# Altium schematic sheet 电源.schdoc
size 420 x 297 mm; Symbol: Drawing-Symbol_A4; Company: 嘉立创EDA; Version: V1.0; Page Size: A4; @Project Name: FOC; @Update Date: 2026-07-14; @Create Date: 2026-07-14; Device: Drawing-Symbol_A4; @Board Name: Board1; @Page Name: P1; @Create Time: 03:45:48; @Page Count: 1; @Page No: 1; @Schematic Name: Schematic1; @Update Time: 03:45:48; @Assembly Variant: Basic; Border: 1; Title Block Position: 3; Size: A4; Width: 1655; Height: 1170; Region Start: 1; X Region Count: 6; Y Region Count: 4; Blade Width: 10
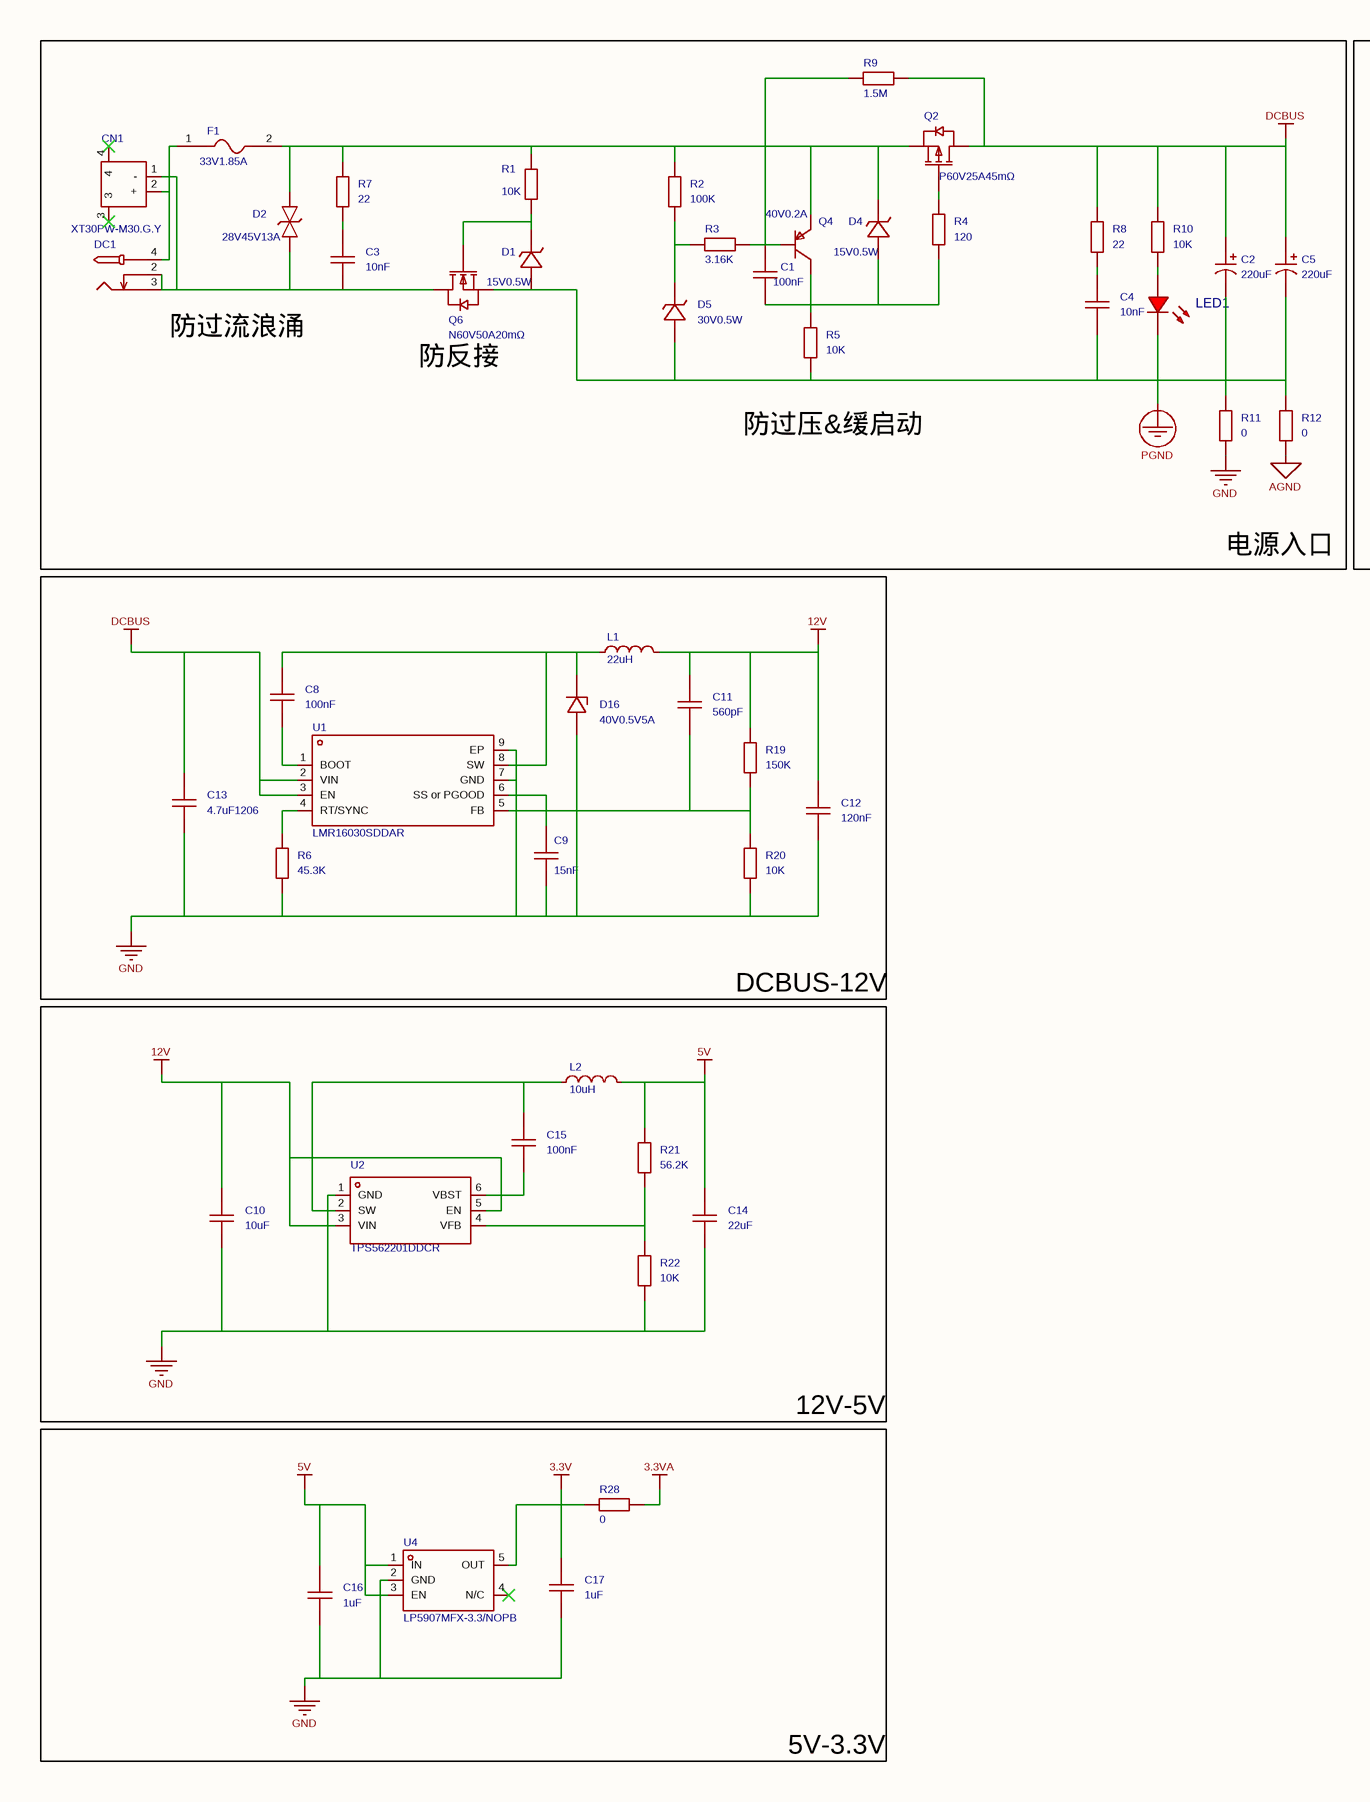
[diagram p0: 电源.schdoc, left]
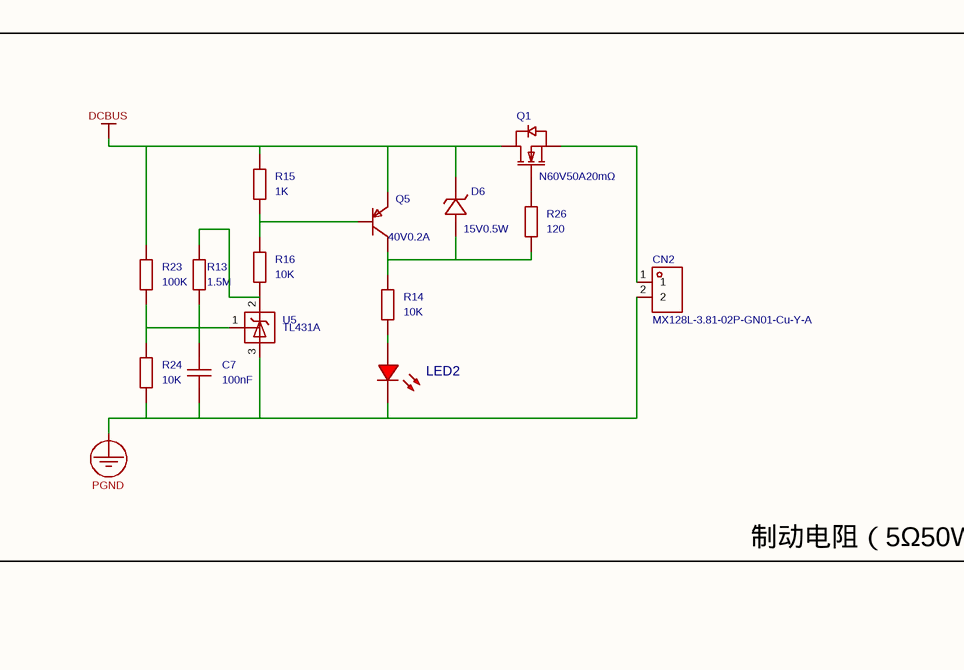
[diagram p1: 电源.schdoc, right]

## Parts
C1  100nF  [C0603]
C2  220uF  [CAP-SMD_BD10.0-L10.3-W10.3-FD-LS11.0]
C3  10nF  [C0603]
C4  10nF  [C0603]
C5  220uF  [CAP-SMD_BD10.0-L10.3-W10.3-FD-LS11.0]
C7  100nF  [C0603]
C8  100nF  [C0603]
C9  15nF  [C0603]
C10  10uF  [C0603]
C11  560pF  [C0603]
C12  120nF  [C0603]
C13  4.7uF1206  [C1206]
C14  22uF  [C0603]
C15  100nF  [C0603]
C16  1uF  [C0603]
C17  1uF  [C0603]
CN1  XT30PW-M30.G.Y  [CONN-TH_XT30PW-M]
CN2  MX128L-3.81-02P-GN01-Cu-Y-A  [CONN-TH_2P-P3.81_MX128L-3.81-GN01-02P-CU-Y-A]
D1  15V0.5W  [LL-34_L3.5-W1.5-RD-2]
D2  28V45V13A  [SMB_L4.6-W3.6-LS5.4-BI]
D4  15V0.5W  [LL-34_L3.5-W1.5-RD-2]
D5  30V0.5W  [LL-34_L3.5-W1.5-RD]
D6  15V0.5W  [LL-34_L3.5-W1.5-RD-2]
D16  40V0.5V5A  [SMA_L4.3-W2.6-LS5.0-FD]
DC1  (no value)  [DC-2.0]
F1  33V1.85A  [F2920]
L1  22uH  [IND-SMD_L5.5-W5.2]
L2  10uH  [IND-SMD_L4.4-W4.2]
LED1  (no value)  [LED_0603]
LED2  (no value)  [LED_0603]
Q1  N60V50A20mΩ  [TO-252-2_L6.6-W6.1-P4.57-LS10.1-TL-CW]
Q2  P60V25A45mΩ  [TO-252-2_L6.6-W6.1-P4.57-LS9.9-TL-CW]
Q4  40V0.2A  [SOT-23-3_L2.9-W1.3-P1.90-LS2.4-BR]
Q5  40V0.2A  [SOT-23-3_L2.9-W1.3-P1.90-LS2.4-BR]
Q6  N60V50A20mΩ  [TO-252-2_L6.6-W6.1-P4.57-LS10.1-TL-CW]
R1  10K  [R0603]
R2  100K  [R0603]
R3  3.16K  [R0603]
R4  120  [R0603]
R5  10K  [R0603]
R6  45.3K  [R0603]
R7  22  [R0603]
R8  22  [R0603]
R9  1.5M  [R0603]
R10  10K  [R0603]
R11  0  [R0603]
R12  0  [R0603]
R13  1.5M  [R0603]
R14  10K  [R0603]
R15  1K  [R0603]
R16  10K  [R0603]
R19  150K  [R0603]
R20  10K  [R0603]
R21  56.2K  [R0603]
R22  10K  [R0603]
R23  100K  [R0603]
R24  10K  [R0603]
R26  120  [R0603]
R28  0  [R0603]
U1  LMR16030SDDAR  [SOIC-8_L4.9-W3.9-P1.27-LS6.0-BL-EP2.3]
U2  TPS562201DDCR  [SOT-23-6_L2.9-W1.6-P0.95-LS2.8-BR]
U4  LP5907MFX-3.3/NOPB  [SOT-23-5_L3.0-W1.7-P0.95-LS2.8-BR]
U5  TL431A  [SOT-23-3_L3.0-W1.7-P0.95-LS2.9-BR]

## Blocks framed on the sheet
制动电阻（5Ω50W）: C7 CN2 D6 LED2 Q1 Q5 R13-R16 R23 R24 R26 U5
DCBUS-12V: C8 C9 C11-C13 D16 L1 R6 R19 R20 U1

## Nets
3.3V: C17.2 R28.1 U4.5(OUT)
3.3VA: R28.2
5V: C14.2 C16.2 L2.2 R21.2 U4.1(IN) U4.3(EN)
12V: C10.2 C11.2 C12.2 L1.2 R19.2 U2.3(VIN) U2.5(EN)
AGND: R12.1
DCBUS: C2.1 C5.1 C13.2 D6.1(K) Q1.2(D) Q2.2(D) Q5.2(E) R8.2 R9.2 R10.2 R15.2 R23.2 U1.2(VIN) U1.3(EN)
GND: C9.1 C10.1 C12.1 C13.1 C14.1 C16.1 C17.1 D16.1(A) R6.1 R11.1 R20.1 R22.1 U1.7(GND) U1.9(EP) U2.1(GND) U4.2(GND)
PGND: C2.2 C4.1 C5.2 C7.1 CN2.2 D1.2(A) D5.2(A) LED1.1(C) LED2.1(C) Q6.3(S) R5.1 R11.2 R12.2 R24.1 U5.3(A)
NetC1_1: C1.1 D4.2(A) Q4.3(C) R4.1 R5.2
NetC1_2: C1.2 Q4.1(B) R3.2 R9.1
NetC3_1: C3.1 CN1.1(-) D2.1 DC1.2 DC1.3 Q6.2(D)
NetC3_2: C3.2 R7.1
NetC4_2: C4.2 R8.1
NetC7_2: C7.2 R13.1 R23.1 R24.2 U5.1(R)
NetC8_1: C8.1 U1.1(BOOT)
NetC8_2: C8.2 D16.2(K) L1.1 U1.8(SW)
NetC9_2: C9.2 U1.6(SS_or_PGOOD)
NetC11_1: C11.1 R19.1 R20.2 U1.5(FB)
NetC15_1: C15.1 U2.6(VBST)
NetC15_2: C15.2 L2.1 U2.2(SW)
NetCN1_2: CN1.2(+) DC1.4 F1.1
NetCN2_1: CN2.1 Q1.3(S)
NetD1_1: D1.1(K) Q6.1(G) R1.1
NetD2_2: D2.2 D4.1(K) F1.2 Q2.3(S) Q4.2(E) R1.2 R2.2 R7.2
NetD5_1: D5.1(C) R2.1 R3.1
NetD6_2: D6.2(A) Q5.3(C) R14.1 R26.1
NetLED1_2: LED1.2(A) R10.1
NetLED2_2: LED2.2(A) R14.2
NetQ1_1: Q1.1(G) R26.2
NetQ2_1: Q2.1(G) R4.2
NetQ5_1: Q5.1(B) R15.1 R16.1
NetR6_2: R6.2 U1.4(RT/SYNC)
NetR13_2: R13.2 R16.2 U5.2(K)
NetR21_1: R21.1 R22.2 U2.4(VFB)

Not connected (* = marked no-connect by the designer): CN1 3* 4*; U4 4(N/C)*

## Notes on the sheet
- (near DC1) 防过流浪涌
- (near Q6) 防反接
- (near R5) 防过压&缓启动
- 电源入口
- 12V-5V
- 5V-3.3V

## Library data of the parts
C1 C3 C4 = CAP_0603: Symbol: Capacitance; ConvertToPcb: yes; ModelId: ac125912035d415993ca9572d50418b10819f05c4eef4c71ace90d822a990e87; ModelName: C0603_L1.6-W0.8-H0.8; ModelTransform: 62.992,31.496,0,0,0,0,0,0,0
C2 C5 = JVJ63V220M10x10: 容值:220uF;精度:±20%;额定电压:63V;纹波电流:225mA@120Hz;; Manufacturer: JIERR(捷而瑞); AddInBom: yes; ModelId: c5805980ffa24e6da624be5898d1d67f0819f05c4eef4c71ace90d822a990e87; ModelTransform: 433.07,405.511,0,180,0,0,0,0,0; Tolerance: ±20%; Voltage Rating: 63V; Lifetime: 2000hrs@105℃
C7-C12 C14-C17 = CAP_0603: Symbol: Capacitance; 3D Model: ac125912035d415993ca9572d50418b10819f05c4eef4c71ace90d822a990e87; 3D Model Transform: 62.992,31.496,0,0,0,0,0,0,0; ConvertToPcb: yes; ModelName: C0603_L1.6-W0.8-H0.8
C13 = CAP_1206: Symbol: Capacitance; 3D Model: e4be705b945545a48e666415e3682bd80819f05c4eef4c71ace90d822a990e87; 3D Model Transform: 125.984,62.992,0,0,0,0,0,0,0; ConvertToPcb: yes; ModelName: C1206_L3.2-W1.6-H1.3
CN1 = XT30PW-M30.G.Y: Socket,DCsupply,XT30,male,PIN:2; Manufacturer: AMASS(艾迈斯); AddInBom: yes; ModelId: 722652c2597f41cd937322584dc4b29b0819f05c4eef4c71ace90d822a990e87; ModelTransform: 523.621,549.2115,0,0,0,0,-0.005,-39.568,-78.74; Rated current: 15A; Rated voltage: 500VDC; Connector type: 航模插头; Wire gauge: 16/18/20AWG; contact resistance: 1.2mΩ; interface form: 公头
CN2 = MX128L-3.81-02P-GN01-Cu-Y-A: 结构:1x2P;间距:3.81mm;颜色:绿色;安装方式:直插;排数:1;每排PIN数:2;额定电流:10A;额定电压:150V;线规 - AWG:16~26;线规 - 平方毫米:1.5;工作温度范围:-40℃~+105℃;; Manufacturer: MAX(迈旭); Symbol: MX128L-3.81-GN01-02P-CU-Y-A; 3D Model: 3ada76795bf04056bedcd0ec9f9046df0819f05c4eef4c71ace90d822a990e87; 3D Model Transform: 300.3931,291.338,0,0,0,0,0,-11.811,-137.795; Structure: 1x2P; Pitch: 3.81mm; Number of PINs Per Row: 2; Screw Specification: M2; Current Rating (Max): 10A; Voltage Rating (Max): 150V; Wire Gauge - AWG: 16~26; Wire Gauge - mm2: 1.5; AddInBom: yes
D1 = ZMM15V: 二极管配置:1个独立式;稳压值(标称值):15V;稳压值(范围):13.8V~15.6V;耗散功率(Pd):500mW;; Manufacturer: YONGYUTAI(永裕泰); AddInBom: yes; ModelId: cdb89680927740768e9f4c53865b044a0819f05c4eef4c71ace90d822a990e87; ModelTransform: 137.795,59.055,0,0,0,0,0,0,0; Diode Configuration: 1个独立式; Zener Voltage(Nom): 15V; Reverse Leakage Current (Ir): 100nA@11V; Pd - Power Dissipation: 500mW; Impedance(Zzt): 30Ω; Impedance(Zzk): 110Ω; Operating Junction Temperature Range: -55℃~+150℃
D2 = SMBJ28CA_C19077583: 极性:双向;反向截止电压(Vrwm):28V;钳位电压:45.4V;峰值脉冲电流(Ipp):13.22A@10/1000us;峰值脉冲功率(Ppp):600W@10/1000us;击穿电压:34.4V;; Manufacturer: R+O(宏嘉诚); AddInBom: yes; ModelId: 56a671846d664f15ac0751d5510bb56a0819f05c4eef4c71ace90d822a990e87; ModelTransform: 212.598,142.5194,0,0,0,0,0,0,0; Polarity: 双向; Reverse Stand-Off Voltage (Vrwm): 28V; Clamping Voltage: 45.4V; Voltage - Breakdown: 34.4V; Reverse Leakage Current (Ir): 5uA; level of protection: IEC 61000-4-2; Type: TVS
D4 D6 = ZMM15V: 二极管配置:1个独立式;稳压值(标称值):15V;稳压值(范围):13.8V~15.6V;耗散功率(Pd):500mW;; Manufacturer: YONGYUTAI(永裕泰); 3D Model: cdb89680927740768e9f4c53865b044a0819f05c4eef4c71ace90d822a990e87; 3D Model Transform: 137.795,59.055,0,0,0,0,0,0,0; Diode Configuration: 1个独立式; Zener Voltage(Nom): 15V; Reverse Leakage Current (Ir): 100nA@11V; Pd - Power Dissipation: 500mW; Impedance(Zzt): 30Ω; Impedance(Zzk): 110Ω; Operating Junction Temperature Range: -55℃~+150℃; AddInBom: yes
D5 = ZMM30V: 二极管配置:1个独立式;稳压值(标称值):30V;稳压值(范围):28V~32V;耗散功率(Pd):500mW;; Manufacturer: JSMSEMI(杰盛微); AddInBom: yes; ModelId: 4a6f2309ca4c4217857da1816cccdf690819f05c4eef4c71ace90d822a990e87; ModelName: LL-34_L3.5-W1.5; ModelTransform: 133.93674,59.031,0,0,0,0,0,0,0; Diode Configuration: 1个独立式; Zener Voltage(Nom): 30V; Reverse Leakage Current (Ir): 100nA@22V; Pd - Power Dissipation: 500mW; Impedance(Zzt): 80Ω; Impedance(Zzk): 220Ω
D16 = SS54_C7420369: 二极管配置:独立式;正向压降(Vf):550mV@5A;直流反向耐压(Vr):40V;整流电流:5A;; Manufacturer: R+O(宏嘉诚); 3D Model: 7e24bebe6cd74171ae8c9de6fc5b78aa0819f05c4eef4c71ace90d822a990e87; 3D Model Transform: 198.4248,103.5431,0,180,0,0,-0.001,0,0; Diode Configuration: 独立式; Voltage - DC Reverse(Vr): 40V; Current - Rectified: 5A; Reverse Leakage Current (Ir): 50uA@40V; Operating Junction Temperature Range: -55℃~+125℃; Non-Repetitive Peak Forward Surge Current: 120A; AddInBom: yes
DC1 = DC-005_2.0: Symbol: DC电源接口; ConvertToPcb: yes; ModelId: f5f20b8a2308479b936ba3c2698865bb0819f05c4eef4c71ace90d822a990e87; ModelName: DC-IN-TH_DC-5520-1; ModelTransform: 372.05,551.18,582.68,90,0,0,137.8,0,-149.61
F1 = SMD2920P185TF: 耐压(Vmax):33V;最大电流(Imax):40A;保持电流(Ihold):1.85A;跳闸电流(Itrip):3.7A;; Manufacturer: RUILON(瑞隆源); AddInBom: yes; ModelId: c20979b6eed84fe694c25fdbe1326c050819f05c4eef4c71ace90d822a990e87; ModelName: F2920-1; ModelTransform: 289.7632,201.5744,0,0,0,0,0,0,0; Voltage - Max: 33V; Current - Max: 40A; Hold Current: 1.85A; Trip Current: 3.7A; Power Dissipation: 1.5W; Resistance - Initial (Ri) (Min): 30mΩ; Resistance - Post Trip (R1) (Max): 150mΩ; Time to Trip(Max): 2.5s
L1 = SMMS0530-220M: 电感值:22uH;精度:±20%;额定电流:1.8A;饱和电流(Isat):2A;类型:-;; Manufacturer: SXN(顺翔诺); AddInBom: yes; ModelId: 8807b4a3401f4609bbc4ad95ff9613320819f05c4eef4c71ace90d822a990e87; ModelName: IND-SMD_L5.5-W5.2-H3.0; ModelTransform: 216.535,204.724,0,0,0,0,0,0,0; Tolerance: ±20%; Current Rating: 1.8A; Current - Saturation(Isat): 2A; DC Resistance(DCR): 394.8mΩ
L2 = FXL0420-100-M: 电感值:10uH;精度:±20%;额定电流:1.6A;饱和电流(Isat):2.2A;类型:一体成型电感;; Manufacturer: cjiang(长江微电); AddInBom: yes; ModelId: e9b3d3f4fa134185b54d517730715f160819f05c4eef4c71ace90d822a990e87; ModelName: IND-SMD_L4.2-W4.4-H2.0; ModelTransform: 173.228,165.354,0,0,0,0,0,0,0; Tolerance: ±20%; Current Rating: 1.6A; Current - Saturation(Isat): 2.2A; DC Resistance(DCR): 282mΩ; Type: 一体成型电感
LED1 LED2 = LED_0603-R: Symbol: LED_R; Convert to PCB: yes; 3D Model: dd8257b0d61a4cd7b68939a056e080950819f05c4eef4c71ace90d822a990e87; 3D Model Transform: 58.72,29.4,22.03,0,0,0,0,0,0; ModelName: LED-0603_R
Q1 Q6 = NCE6050KA: 数量:1个N沟道;漏源电压(Vdss):60V;连续漏极电流(Id):50A;导通电阻(RDS(on)):20mΩ@10V,20A;耗散功率(Pd):85W;阈值电压(Vgs(th)):2.5V;; Manufacturer: NCE(无锡新洁能); AddInBom: yes; ModelId: 5d8ef1b124a64febb2ca91a0282fbfcc0819f05c4eef4c71ace90d822a990e87; ModelTransform: 397.637,259.842,0,0,0,0,38.819,0,0; Number: 1个N沟道; Drain to Source Voltage: 60V; Current - Continuous Drain(Id): 50A; Pd - Power Dissipation: 85W; Gate Threshold Voltage (Vgs(th)): 2.5V; Gate Charge(Qg): 50nC@30V; Input Capacitance(Ciss): 2.05nF@30V; Reverse Transfer Capacitance (Crss@Vds): 120pF
Q2 = NCE60P25K: 数量:1个P沟道;漏源电压(Vdss):60V;连续漏极电流(Id):25A;导通电阻(RDS(on)):45mΩ@10V;耗散功率(Pd):90W;阈值电压(Vgs(th)):3.5V;; Manufacturer: NCE(无锡新洁能); AddInBom: yes; ModelId: ce57f84d66384067af8a68020b6de06d0819f05c4eef4c71ace90d822a990e87; ModelName: TO-252-2L-3P_L6.6-W6.1-H2.3-LS10.1-P4.6; ModelTransform: 259.842,390.52442,0,270,0,0,38.027,-0.598,0; Number: 1个P沟道; Drain to Source Voltage: 60V; Current - Continuous Drain(Id): 25A; Pd - Power Dissipation: 90W; Gate Threshold Voltage (Vgs(th)): 3.5V; Gate Charge(Qg): 46nC@10V; Input Capacitance(Ciss): 3.43nF; Type: P沟道; Output Capacitance(Coss): 391pF
Q4 = MMBT3906_C7420354: 晶体管类型:PNP;集电极电流(Ic):200mA;集射极击穿电压(Vceo):40V;耗散功率(Pd):200mW;直流电流增益(hFE):100@10mA,1.0V;; Manufacturer: R+O(宏嘉诚); AddInBom: yes; ModelId: c62791f0466c4ae2a892c056b845b0ca0819f05c4eef4c71ace90d822a990e87; ModelName: SOT-23-3P_L2.9-W1.3-H1.0-LS2.4-P0.95; ModelTransform: 98.425,114.173,0,180,0,0,0.0005,-0.0005,0; type: PNP; Current - Collector(Ic): 200mA; Collector - Emitter Voltage VCEO: 40V; Pd - Power Dissipation: 200mW; Transition frequency(fT): 300MHz; Current - Collector Cutoff: 100nA; Vce Saturation(VCE(sat)): 300mV; Emitter-Base Voltage(Vebo): 5V
Q5 = MMBT3906_C7420354: 晶体管类型:PNP;集电极电流(Ic):200mA;集射极击穿电压(Vceo):40V;耗散功率(Pd):200mW;直流电流增益(hFE):100@10mA,1.0V;; Manufacturer: R+O(宏嘉诚); 3D Model: c62791f0466c4ae2a892c056b845b0ca0819f05c4eef4c71ace90d822a990e87; 3D Model Transform: 98.425,114.173,0,180,0,0,0.0005,-0.0005,0; type: PNP; Current - Collector(Ic): 200mA; Collector - Emitter Voltage VCEO: 40V; Pd - Power Dissipation: 200mW; Transition frequency(fT): 300MHz; Current - Collector Cutoff: 100nA; Vce Saturation(VCE(sat)): 300mV; Emitter-Base Voltage(Vebo): 5V; AddInBom: yes; ModelName: SOT-23-3P_L2.9-W1.3-H1.0-LS2.4-P0.95
R1 = Res_0603: Symbol: 电阻; ConvertToPcb: yes; ModelId: fc143cca1e79419f9cd78b61e9279f080819f05c4eef4c71ace90d822a990e87; ModelTransform: 31.8897,63.7794,0,90,0,0,0,0,0
R2-R16 R19-R24 R26 R28 = Res_0603: Symbol: 电阻; 3D Model: fc143cca1e79419f9cd78b61e9279f080819f05c4eef4c71ace90d822a990e87; 3D Model Transform: 31.8897,63.7794,0,90,0,0,0,0,0; ConvertToPcb: yes
U1 = LMR16030SDDAR: 功能类型:降压型;工作电压:4.3V~60V;输出电压:800mV~50V;输出电流:3A;输出类型:可调;; Manufacturer: TI(德州仪器); AddInBom: yes; ModelId: ba240e69e1f440f79b85bd6e5ae1d4fa0819f05c4eef4c71ace90d822a990e87; ModelTransform: 192.913,236.22,0,0,0,0,0,0,0; Function: 降压型; Output Current: 3A; Frequency - Switching: 2.5MHz; Synchronous Rectifier: 否; Number of Outputs: 1; Topology: 降压式; Quiescent Current: 40uA; Switch tube (built-in/external): 内置; Output Type: 可调
U2 = TPS562201DDCR: 功能类型:降压型;工作电压:4.5V~17V;输出电压:768mV~7V;输出电流:2A;输出类型:可调;; Manufacturer: TI(德州仪器); AddInBom: yes; ModelId: 18da8f6c14a34920b3e136b5c401a1190819f05c4eef4c71ace90d822a990e87; ModelName: SOT-23-6_L2.9-W1.6-H1.5-LS2.8-P0.95; ModelTransform: 110.73671,114.173,0,180,0,0,0.001,-0.003,0; Function: 降压型; Output Current: 2A; Frequency - Switching: 580kHz; Synchronous Rectifier: 是; Number of Outputs: 1; Topology: 降压式; Quiescent Current: 380uA; Switch tube (built-in/external): 内置; Output Type: 可调
U4 = LP5907MFX-3.3/NOPB: 输出极性:正极;工作电压:5.5V;输出电压:3.3V;输出电流:250mA;电源纹波抑制比(PSRR):82dB@(1kHz);输出类型:固定;; Manufacturer: TI(德州仪器); AddInBom: yes; ModelId: 0a2a1b8f50944f73965918ad6e5fe1670819f05c4eef4c71ace90d822a990e87; ModelName: SOT-23-5_L2.9-W1.6-H1.1-LS2.8-P0.95; ModelTransform: 114.173,109.636,0,180,0,0,0,0,0; Output Configuration: 正极; Voltage - Supply: 5.5V; Output Voltage: 3.3V; Output Current: 250mA; Voltage Dropout: 250mV@(250mA); standby current: 12uA; Noise: 10uVrms; Output Type: 固定; Number of Outputs: 1
U5 = TL431A_C54830631: 输出类型:可调;工作电压:2.5V~36V;输出电压:2.5V~36V;输出电流:150mA;精度:±0.5%;; Manufacturer: R+O(宏嘉诚); AddInBom: yes; ModelId: 89cb27a44ab2466697082bb9fd73a7d00819f05c4eef4c71ace90d822a990e87; ModelName: SOT-23-3L_L2.9-W1.6-H1.1-LS2.8-P0.95; ModelTransform: 114.173,110.236,0,90,0,0,0,0,0; Output Type: 可调; Output Current: 150mA; Tolerance: ±0.5%; Reference Type: 并联; Quiescent Current: 1uA; Minimum Cathode Current for Regulation: 250uA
